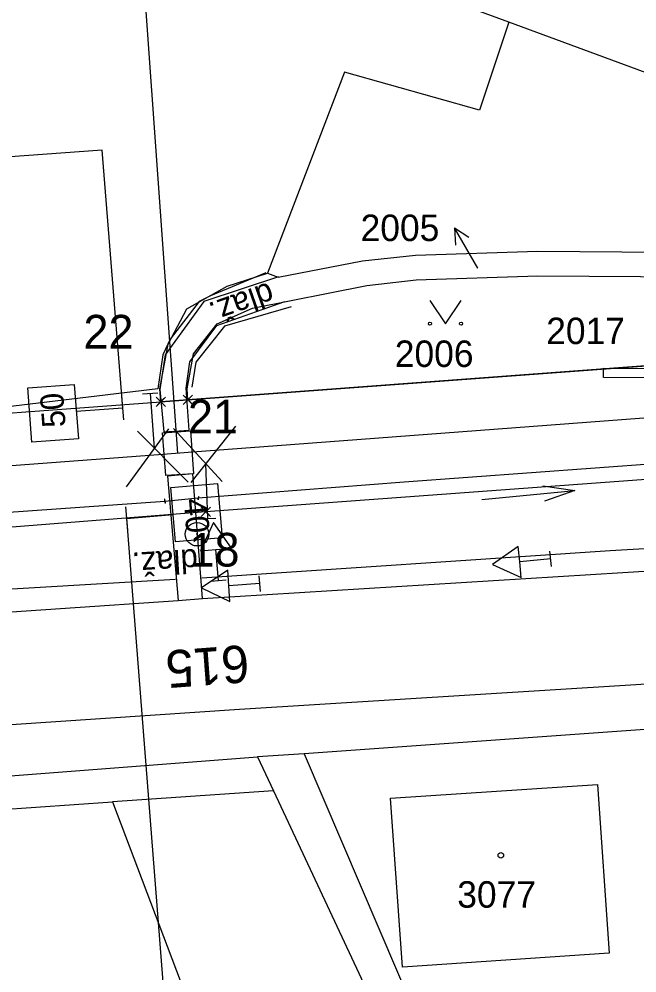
# Model space of a CAD drawing. Extents: x -779302 to -774398, y -1144902 to -1142831.
# Drawn here: x -774881.1 to -774841.4, y -1144467.9 to -1144406.7 of the extents above; entities that cross this region are included whole.
import ezdxf

# ---------------------------------------------------------------- set-up
doc = ezdxf.new("R2010")
doc.units = 0
for name, color, linetype in [('Hranice parcel', 7, 'Continuous'), ('legenda I_5_2 - Vrstva 53', 7, 'Continuous'), ('Parcelní čísla', 7, 'Continuous'), ('Pop  PČ popisy', 7, 'Continuous'), ('SŽDC', 7, 'Continuous'), ('Vnitřní kresba', 7, 'Continuous'), ('zjednodus_g_situ-seda - Vrstva 1', 7, 'Continuous'), ('zjednodus_g_situ-seda - Vrstva 13', 7, 'Continuous'), ('zjednodus_g_situ-seda - Vrstva 17', 7, 'Continuous'), ('zjednodus_g_situ-seda - Vrstva 19', 7, 'Continuous'), ('zjednodus_g_situ-seda - Vrstva 4', 7, 'Continuous'), ('zjednodus_g_situ-seda - Vrstva 5', 7, 'Continuous'), ('zjednodus_g_situ-seda - Vrstva 51', 7, 'Continuous'), ('zjednodus_g_situ-seda - Vrstva 63', 7, 'Continuous'), ('zjednodus_g_situ-seda - Vrstva 9', 7, 'Continuous'), ('Značky budov', 7, 'Continuous'), ('Značky kultur', 7, 'Continuous')]:
    doc.layers.add(name, color=color, linetype=linetype)

msp = doc.modelspace()

# ---------------------------------------------------------------- linework, layer by layer
at = {"layer": 'Hranice parcel'}
for p, q in [((-774832.66, -1144428.33), (-774870.21, -1144431.11)), ((-774870.21, -1144431.11), (-774871.96, -1144431.24)), ((-774838.77, -1144452.13), (-774862.75, -1144453.84)), ((-774934.19, -1144459.28), (-774865.74, -1144454.05)), ((-774862.75, -1144453.84), (-774865.74, -1144454.05)), ((-774865.74, -1144454.05), (-774864.71, -1144456.23)), ((-774864.71, -1144456.23), (-774875.06, -1144456.94)), ((-774934.36, -1144461.03), (-774875.06, -1144456.94))]:
    msp.add_line(p, q, dxfattribs=at)
for points in [[(-774871.96, -1144431.24), (-774872.02, -1144430.41), (-774871.48, -1144427.55), (-774870.28, -1144425.27), (-774867.69, -1144423.82), (-774865.1, -1144422.99), (-774864.41, -1144423.23), (-774859, -1144422.2), (-774855.6, -1144421.82), (-774847.74, -1144421.57), (-774831.56, -1144421.69), (-774828.44, -1144421.43)], [(-774870.21, -1144431.11), (-774870.26, -1144430.4), (-774869.86, -1144428.16), (-774868.34, -1144426.23), (-774866.07, -1144425.23), (-774858.72, -1144423.78), (-774855.55, -1144423.4), (-774847.74, -1144423.16), (-774831.25, -1144423.26), (-774829.7, -1144422.88), (-774828.44, -1144421.43)], [(-775003.31, -1144440.57), (-774957.77, -1144437.47), (-774890.46, -1144432.61), (-774871.96, -1144431.24)], [(-774832.04, -1144435.58), (-774869.06, -1144438.3), (-774919.16, -1144442.27), (-774942.23, -1144444.12), (-775006.07, -1144448.84), (-775047.73, -1144454.47), (-775049.08, -1144458.29), (-775076.86, -1144459.23)], [(-774862.75, -1144453.84), (-774849.63, -1144484.54), (-774831.53, -1144484.37)], [(-774843.9, -1144455.82), (-774843.17, -1144466.65), (-774856.44, -1144467.55), (-774857.21, -1144456.69), (-774843.9, -1144455.82)], [(-774864.71, -1144456.23), (-774857.67, -1144471.28), (-774851.11, -1144488.59), (-774841.56, -1144519.55)], [(-774875.06, -1144456.94), (-774861.71, -1144492.14), (-774848.12, -1144528.64), (-774837.33, -1144580.31), (-774836.58, -1144588.82), (-774838.41, -1144597.12), (-774842.25, -1144608.21), (-774846.04, -1144615.37)]]:
    msp.add_lwpolyline(points, dxfattribs=at)
at = {"layer": 'legenda I_5_2 - Vrstva 53'}
msp.add_lwpolyline([(-774957.77, -1144437.47), (-774890.46, -1144432.61), (-774871.96, -1144431.24), (-774870.21, -1144431.11), (-774832.66, -1144428.33), (-774832.04, -1144435.58), (-774869.06, -1144438.3), (-774919.16, -1144442.27), (-774942.23, -1144444.12)], dxfattribs=at)
at = {"layer": 'Pop  PČ popisy'}
for p, q in [((-774851.6, -1144422.66), (-774853.1, -1144420.061)), ((-774853.1, -1144420.061), (-774852.166, -1144420.678)), ((-774853.1, -1144420.061), (-774853.033, -1144421.179)), ((-774851.6, -1144422.67), (-774851.6, -1144422.66))]:
    msp.add_line(p, q, dxfattribs=at)
at = {"layer": 'SŽDC'}
for p, q in [((-774871.76, -1144431.44), (-774872.26, -1144430.94)), ((-774871.76, -1144431.04), (-774872.26, -1144431.54)), ((-774872.16, -1144431.44), (-774871.66, -1144430.94)), ((-774872.16, -1144431.04), (-774871.66, -1144431.54)), ((-774870.01, -1144431.31), (-774870.51, -1144430.81)), ((-774870.01, -1144430.91), (-774870.51, -1144431.41)), ((-774870.41, -1144431.31), (-774869.91, -1144430.81)), ((-774870.41, -1144430.91), (-774869.91, -1144431.41)), ((-774871.96, -1144431.24), (-774871.96, -1144431.24)), ((-774870.21, -1144431.11), (-774870.21, -1144431.11)), ((-774868.86, -1144438.5), (-774869.36, -1144438)), ((-774868.86, -1144438.1), (-774869.36, -1144438.6)), ((-774869.26, -1144438.5), (-774868.76, -1144438)), ((-774869.26, -1144438.1), (-774868.76, -1144438.6)), ((-774869.06, -1144438.3), (-774869.06, -1144438.3))]:
    msp.add_line(p, q, dxfattribs=at)
msp.add_lwpolyline([(-774957.77, -1144437.47), (-774890.46, -1144432.61), (-774871.96, -1144431.24), (-774870.21, -1144431.11), (-774832.66, -1144428.33), (-774832.04, -1144435.58), (-774869.06, -1144438.3), (-774919.16, -1144442.27), (-774942.23, -1144444.12)], dxfattribs=at)
at = {"layer": 'Vnitřní kresba'}
for p, q in [((-774849.61, -1144406.86), (-774870.95, -1144398.98)), ((-774849.61, -1144406.86), (-774851.49, -1144412.52)), ((-774830.99, -1144413.74), (-774849.61, -1144406.86)), ((-774860.16, -1144410.07), (-774865.1, -1144422.99)), ((-774851.49, -1144412.52), (-774860.16, -1144410.07))]:
    msp.add_line(p, q, dxfattribs=at)
at = {"layer": 'zjednodus_g_situ-seda - Vrstva 1'}
msp.add_lwpolyline([(-774830.163, -1144431.482), (-774850.563, -1144433.022), (-774864.475, -1144434.064), (-774869.912, -1144434.473), (-774871.827, -1144434.617), (-774885.853, -1144435.682), (-774900.88, -1144436.804), (-774924.49, -1144438.587), (-774948.039, -1144440.364), (-774972.389, -1144442.197), (-774996.531, -1144444.018), (-775020.057, -1144445.789), (-775040.384, -1144447.314), (-775053.937, -1144448.326), (-775072.564, -1144449.732), (-775089.145, -1144450.956), (-775106.822, -1144452.299), (-775129.866, -1144454.038), (-775154.332, -1144455.872), (-775163.87, -1144456.589), (-775186.746, -1144458.314), (-775211.372, -1144460.168), (-775237.518, -1144462.13)], dxfattribs=at)
at = {"layer": 'zjednodus_g_situ-seda - Vrstva 13'}
for p, q in [((-774837.85, -1144435.049), (-774856.327, -1144436.41)), ((-774856.327, -1144436.41), (-774869.548, -1144437.441)), ((-774851.345, -1144437.507), (-774845.372, -1144436.944))]:
    msp.add_line(p, q, dxfattribs=at)
for points in [[(-774847.41, -1144436.634), (-774845.372, -1144436.944), (-774847.316, -1144437.63)], [(-774871.7, -1144437.646), (-774885.67, -1144438.638), (-774900.901, -1144439.759), (-774924.226, -1144441.559), (-774947.713, -1144443.292), (-774972.002, -1144445.163), (-774996.171, -1144446.963), (-775023.261, -1144448.853)]]:
    msp.add_lwpolyline(points, dxfattribs=at)
at = {"layer": 'zjednodus_g_situ-seda - Vrstva 17'}
msp.add_line((-774865.219, -1144422.955), (-774868.763, -1144424.44), dxfattribs=at)
for points in [[(-774868.763, -1144424.44), (-774869.5, -1144424.797), (-774871.355, -1144427.21), (-774871.821, -1144428.237), (-774872.154, -1144430.412)], [(-774863.59, -1144425.134), (-774867.858, -1144426.391), (-774869.712, -1144428.693), (-774869.973, -1144430.293)], [(-774872.154, -1144430.412), (-774885.89, -1144432.054), (-774902.942, -1144433.126), (-774924.674, -1144434.792), (-774949.136, -1144436.402), (-774972.464, -1144437.97), (-774996.34, -1144439.603), (-775002.854, -1144440.114), (-775020.655, -1144440.349), (-775032.337, -1144440.732), (-775032.737, -1144440.939), (-775036.851, -1144438.197), (-775060.184, -1144440.14)], [(-774711.09, -1144432.438), (-774721.001, -1144433.51), (-774746.695, -1144435.165), (-774782.311, -1144437.164), (-774812.632, -1144439.027), (-774843.087, -1144440.809), (-774869.315, -1144442.558)], [(-774871.015, -1144442.651), (-774889.508, -1144443.752), (-774891.181, -1144441.839)]]:
    msp.add_lwpolyline(points, dxfattribs=at)
at = {"layer": 'zjednodus_g_situ-seda - Vrstva 19'}
msp.add_line((-774869.548, -1144437.441), (-774871.7, -1144437.646), dxfattribs=at)
for centre, major_axis, ratio, start_param, end_param in [((-774871.69, -1144437.616), (-0.024, 0.127), 0.121225, 4.55931, 9.574384), ((-774871.69, -1144437.616), (-0.024, 0.127), 0.121225, 1.782223, 4.55931), ((-774869.542, -1144437.438), (0.024, 0.114), 0.044617, 5.976462, 10.996828), ((-774869.542, -1144437.438), (0.024, 0.114), 0.044617, 4.713643, 7.888897)]:
    msp.add_ellipse(centre, major_axis=major_axis, ratio=ratio, start_param=start_param, end_param=end_param, dxfattribs=at)
at = {"layer": 'zjednodus_g_situ-seda - Vrstva 4'}
for p, q in [((-774870.87, -1144434.545), (-774876.52, -1144355.311)), ((-774872.139, -1144430.68), (-774873.137, -1144430.756)), ((-774872.638, -1144430.718), (-774872.372, -1144434.225)), ((-774870.011, -1144436.425), (-774867.14, -1144432.818)), ((-774871.463, -1144432.986), (-774874.189, -1144436.703)), ((-774870.201, -1144436.4), (-774873.457, -1144433.137)), ((-774871.138, -1144432.963), (-774868.013, -1144436.352)), ((-774868.927, -1144438.737), (-774869.054, -1144435.223)), ((-774869.427, -1144438.755), (-774868.427, -1144438.719))]:
    msp.add_line(p, q, dxfattribs=at)
msp.add_lwpolyline([(-774869.862, -1144435.86), (-774871.625, -1144435.967), (-774871.837, -1144433.244), (-774870.057, -1144433.113), (-774869.862, -1144435.86)], dxfattribs=at)
at = {"layer": 'zjednodus_g_situ-seda - Vrstva 5'}
for p, q in [((-774874.334, -1144432.394), (-774874.448, -1144430.898)), ((-774874.391, -1144431.646), (-774877.382, -1144431.873)), ((-774874.216, -1144437.99), (-774874.088, -1144439.484)), ((-774874.152, -1144438.737), (-774871.163, -1144438.482)), ((-774874.152, -1144438.737), (-774870.546, -1144484.942))]:
    msp.add_line(p, q, dxfattribs=at)
msp.add_lwpolyline([(-774874.391, -1144431.646), (-774875.723, -1144415.079), (-774881.918, -1144415.528), (-774885.557, -1144372.096)], dxfattribs=at)
for points in [[(-774877.515, -1144430.128), (-774877.25, -1144433.618), (-774880.241, -1144433.845), (-774880.506, -1144430.355)], [(-774871.014, -1144440.225), (-774871.312, -1144436.738), (-774868.323, -1144436.483), (-774868.025, -1144439.97)]]:
    msp.add_lwpolyline(points, close=True, dxfattribs=at)
at = {"layer": 'zjednodus_g_situ-seda - Vrstva 51'}
for p, q in [((-774846.864, -1144441.828), (-774846.962, -1144440.832)), ((-774868.744, -1144442.77), (-774867.748, -1144442.686)), ((-774865.556, -1144443.415), (-774865.63, -1144442.417))]:
    msp.add_line(p, q, dxfattribs=at)
for points in [[(-774864.399, -1144423.221), (-774869.201, -1144424.801), (-774871.669, -1144428.237), (-774872.011, -1144430.458), (-774871.755, -1144433.163)], [(-774871.755, -1144433.163), (-774870.133, -1144433.069), (-774870.324, -1144430.374), (-774870.087, -1144428.682), (-774868.366, -1144426.337), (-774863.992, -1144424.804)], [(-774869.279, -1144443.865), (-774869.899, -1144435.868), (-774871.53, -1144436.015), (-774870.843, -1144444.008)], [(-775004.347, -1144452.658), (-774971.588, -1144450.597), (-774948.721, -1144449.09), (-774924.374, -1144447.834), (-774901.093, -1144446.056), (-774870.843, -1144444.008), (-774869.279, -1144443.865), (-774842.281, -1144442.195), (-774812.694, -1144440.35), (-774782.541, -1144438.602), (-774746.419, -1144436.349)], [(-774868.246, -1144442.728), (-774868.415, -1144440.735), (-774867.418, -1144440.651), (-774868.562, -1144438.991), (-774869.411, -1144440.819), (-774868.415, -1144440.735)], [(-774846.913, -1144441.33), (-774848.904, -1144441.524), (-774849.001, -1144440.529), (-774850.645, -1144441.694), (-774848.807, -1144442.519), (-774848.904, -1144441.524)], [(-774865.593, -1144442.916), (-774867.588, -1144443.063), (-774867.661, -1144442.065), (-774869.333, -1144443.191), (-774867.514, -1144444.06), (-774867.588, -1144443.063)], [(-774745.992, -1144443.71), (-774781.922, -1144445.696), (-774812.012, -1144447.535), (-774841.779, -1144449.448), (-774866.91, -1144451.003), (-774884.455, -1144452.175), (-774887.159, -1144455.728)]]:
    msp.add_lwpolyline(points, dxfattribs=at)
at = {"layer": 'zjednodus_g_situ-seda - Vrstva 63'}
msp.add_line((-774869.579, -1144439.742), (-774869.679, -1144439.75), dxfattribs=at)
msp.add_circle((-774869.629, -1144439.746), 0.756, dxfattribs=at)
at = {"layer": 'zjednodus_g_situ-seda - Vrstva 9'}
msp.add_lwpolyline([(-774838.522, -1144428.499), (-774838.524, -1144429.099), (-774838.526, -1144429.699), (-774843.526, -1144429.683), (-774843.524, -1144429.083), (-774838.524, -1144429.099)], dxfattribs=at)
at = {"layer": 'Značky budov'}
msp.add_circle((-774850.117, -1144460.369), 0.175, dxfattribs=at)
at = {"layer": 'Značky kultur'}
msp.add_lwpolyline([(-774854.67, -1144424.729), (-774853.67, -1144426.23), (-774852.67, -1144424.729)], dxfattribs=at)
for centre in [(-774854.67, -1144426.229), (-774852.67, -1144426.229)]:
    msp.add_circle(centre, 0.1, dxfattribs=at)

# ---------------------------------------------------------------- texts
at = {"layer": 'Parcelní čísla'}
for s, p in [('2005', (-774859.124, -1144420.92)), ('2017', (-774847.204, -1144427.538)), ('2006', (-774856.928, -1144429.006)), ('3077', (-774852.917, -1144463.73))]:
    msp.add_text(s, height=1.7, dxfattribs=at).set_placement(p)
at = {"layer": 'SŽDC'}
for s, p in [('22', (-774876.922, -1144427.821)), ('21', (-774870.21, -1144433.27)), ('18', (-774870.114, -1144441.822))]:
    msp.add_text(s, height=2.16, dxfattribs=at).set_placement(p)
at = {"layer": 'zjednodus_g_situ-seda - Vrstva 5'}
for s, rotation, p in [('50', 94.34216, (-774878.061, -1144432.841)), ('40', 274.88059, (-774870.493, -1144437.508))]:
    msp.add_text(s, height=1.5, rotation=rotation, dxfattribs=at).set_placement(p)
at = {"layer": 'zjednodus_g_situ-seda - Vrstva 51'}
for rotation, p in [(199.34265, (-774864.998, -1144423.533)), (183.42265, (-774869.615, -1144440.683))]:
    msp.add_text('dlaž.', height=1.5, rotation=rotation, dxfattribs=at).set_placement(p)
at = {"layer": 'zjednodus_g_situ-seda - Vrstva 63'}
msp.add_text('615', height=2.4, rotation=184.30199, dxfattribs=at).set_placement((-774866.376, -1144446.841))

doc.saveas('drawing.dxf')
